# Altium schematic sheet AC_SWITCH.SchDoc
size A4; DocumentNumber: 10; SheetNumber: 10; SheetTotal: 11; PageSetup: Record=PageOptions¦CenterHorizontal=True¦CenterVertical=True¦PrintScale=0.97¦XCorrection=1.00¦YCorrection=1.00¦PrintKind=0¦BorderSize=5000000¦LeftOffset=5¦BottomOffset=0¦Orientation=1¦PaperLength=1000¦PaperWidth=1000¦Scale=100¦PaperSource=7¦PrintQuality=-4¦MediaType=1¦DitherType=10¦PaperKind=A4¦PrintScaleMode=1; Abteilung: Hard/Software Entwicklung
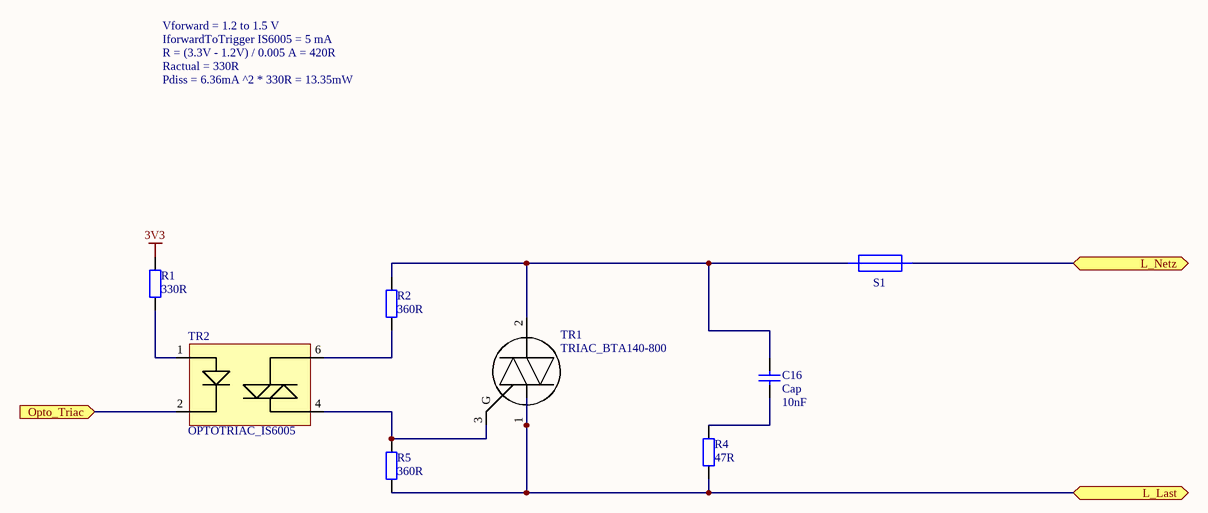
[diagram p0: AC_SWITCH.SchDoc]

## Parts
C16  Cap  value 10nF  [RAD-0.3]
R1  330R  [RLCDT_1206]
R2  360R  [RLCDT_1206]
R4  47R  [RLCDT_1206]
R5  360R  [RLCDT_1206]
S1  SICHERUNGSHALTER_MIRA  [SICHERUNGSHALTER_MIRA]  (value not drawn)
TR1  TRIAC_BTA140-800  [TO-220]
TR2  OPTOTRIAC_IS6005  [DIP-6]

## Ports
L_Last (bidir), L_Netz (bidir), Opto_Triac (in)

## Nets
3V3: R1.1
L_Last: R4.2 R5.2 TR1.1(T1) ; port L_Last
L_Netz: S1.1 ; port L_Netz
Opto_Triac: TR2.2(LED_K) ; port Opto_Triac
NetC16_1: C16.1 R4.1
NetC16_2: C16.2 R2.1 S1.4 TR1.2(T2)
NetR1_2: R1.2 TR2.1(LED_A)
NetR2_2: R2.2 TR2.6(T1)
NetR5_1: R5.1 TR1.3(G) TR2.4(T2)

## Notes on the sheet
- Vforward = 1.2 to 1.5 V
- IforwardToTrigger IS6005 = 5 mA
- R = (3.3V - 1.2V) / 0.005 A = 420R
- Ractual = 330R
- Pdiss = 6.36mA ^2 * 330R = 13.35mW

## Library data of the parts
C16 = Cap: Capacitor
R1 R2 R4 R5 = R: Widerstand
S1 = SICHERUNGSHALTER_MIRA: FUSEHOLDER; B_Bestellnummer: 7851/6
TR2 = OPTOTRIAC_IS600x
